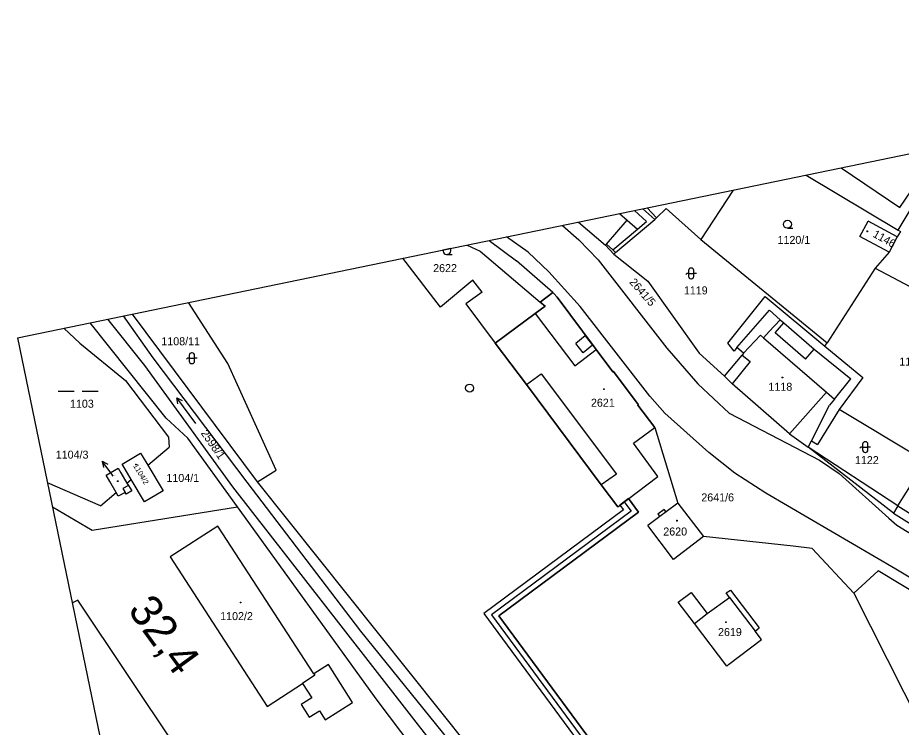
# Model space of a CAD drawing. Extents: x -804166 to -803706, y -1151030 to -1150147.
# Drawn here: x -804166.3 to -804000.6, y -1150280.5 to -1150147.3 of the extents above; entities that cross this region are included whole.
import ezdxf

# ---------------------------------------------------------------- set-up
doc = ezdxf.new("R2010")
doc.units = 0
for name, color, linetype in [('Default', 7, 'Continuous'), ('formát', 7, 'Continuous'), ('kilometráž - vrstava 7', 7, 'Continuous'), ('kn_celek - Cisla parcel pomocna', 7, 'Continuous'), ('kn_celek - Cisla pozemkovych parcel', 7, 'Continuous'), ('kn_celek - Cisla stavebnich parcel', 7, 'Continuous'), ('kn_celek - Hranice parcel', 7, 'Continuous'), ('kn_celek - Vnitrni kresby', 7, 'Continuous'), ('kn_celek - Znacky budov', 7, 'Continuous'), ('kn_celek - Znacky kultur', 7, 'Continuous'), ('plochy - CD', 7, 'Continuous'), ('plochy - SZDC', 7, 'Continuous'), ('plochy - VB', 7, 'Continuous'), ('PSR_C2_2_trasa_Vimperk - Kabelová trasa', 7, 'Continuous')]:
    doc.layers.add(name, color=color, linetype=linetype)

# ---------------------------------------------------------------- blocks, each defined once
blk = doc.blocks.new('803')
at = {"layer": 'Default'}
for p, q in [((-37.9, 0.1), (-7.9, 0.1)), ((7.1, 0.1), (37.1, 0.1))]:
    blk.add_line(p, q, dxfattribs=at)
blk = doc.blocks.new('316')
at = {"layer": 'Default'}
for p, q in [((0.5, 20), (-0.5, 20)), ((-8.3, 10), (-10, 8.1)), ((-5, 10), (-8.3, 10)), ((-5, 15.5), (-5, 4.5)), ((-5, 10), (5, 10)), ((-0.5, 0), (0.5, 0)), ((5, 4.5), (5, 15.5)), ((10, 10), (5, 10))]:
    blk.add_line(p, q, dxfattribs=at)
for centre, start, end in [((-0.5, 15.5), 90, 180), ((0.5, 15.5), 0, 90), ((-0.5, 4.5), 180, 270), ((0.5, 4.5), 270, 0)]:
    blk.add_arc(centre, 4.5, start, end, dxfattribs=at)
blk = doc.blocks.new('304')
at = {"layer": 'Default'}
blk.add_line((-0.1, 0), (9.9, 0), dxfattribs=at)
blk.add_circle((-0.1, 7.5), 7.5, dxfattribs=at)
blk = doc.blocks.new('802')
at = {"layer": 'Default'}
for p, q in [((-30, 0), (30, 0)), ((20, 5), (30, 0)), ((30, 0), (20, -5))]:
    blk.add_line(p, q, dxfattribs=at)
blk = doc.blocks.new('402')
at = {"layer": 'Default'}
for p, q in [((-0.8, 0.8), (0.7, 0.8)), ((-0.8, 0.8), (-0.8, -0.7)), ((0.7, 0.8), (0.7, -0.7)), ((0.7, -0.7), (-0.8, -0.7))]:
    blk.add_line(p, q, dxfattribs=at)
blk = doc.blocks.new('Z61')
at = {"layer": 'Default'}
for p, q in [((0, 0), (30, 0)), ((30, 0), (19.2, 5.3)), ((30, 0), (19.2, -5.3))]:
    blk.add_line(p, q, dxfattribs=at)

msp = doc.modelspace()

# ---------------------------------------------------------------- linework, layer by layer
at = {"layer": 'Default'}
for p, q in [((-804085.16, -1150190.65), (-804086.56, -1150190.94)), ((-804085.82, -1150191.75), (-804084.82, -1150191.75))]:
    msp.add_line(p, q, dxfattribs=at)
msp.add_arc((-804085.82, -1150191), 0.75, 175.2432, 28.0871, dxfattribs=at)
at = {"layer": 'formát'}
for q in [(-803875.43, -1150147.35), (-804123.84, -1150413.06)]:
    msp.add_line((-804166.3, -1150207.4), q, dxfattribs=at)
at = {"layer": 'kilometráž - vrstava 7'}
msp.add_circle((-804081.56, -1150216.84), 0.75, dxfattribs=at)
at = {"layer": 'kn_celek - Cisla parcel pomocna'}
msp.add_line((-804148.4, -1150233.36), (-804148.67, -1150232.99), dxfattribs=at)
at = {"layer": 'kn_celek - Hranice parcel'}
for p, q in [((-804000.88, -1150182.97), (-803994.65, -1150173.69)), ((-804001.24, -1150187.2), (-803993.82, -1150174.86)), ((-804018.48, -1150176.88), (-804001.24, -1150187.2)), ((-804011.92, -1150175.53), (-804000.88, -1150182.97)), ((-804032.16, -1150179.71), (-804038.18, -1150188.96)), ((-804048.27, -1150183.03), (-804046.51, -1150184.91)), ((-804046.51, -1150184.91), (-804044.69, -1150183.13)), ((-804044.69, -1150183.13), (-804038.18, -1150188.96)), ((-804054.22, -1150191.39), (-804046.83, -1150185.22)), ((-804046.83, -1150185.22), (-804046.51, -1150184.91)), ((-804064.14, -1150186.31), (-804061.09, -1150189.04)), ((-804061.17, -1150185.69), (-804056.08, -1150190.02)), ((-804008.37, -1150188.37), (-804006.85, -1150185.52)), ((-804001.37, -1150188.44), (-804006.85, -1150185.52)), ((-804070.61, -1150191.34), (-804074.65, -1150188.48)), ((-804002.9, -1150191.34), (-804008.37, -1150188.37)), ((-804001.37, -1150188.44), (-804002.9, -1150191.34)), ((-804000.78, -1150187.47), (-804001.37, -1150188.44)), ((-804001.24, -1150187.2), (-804000.78, -1150187.47)), ((-804082.03, -1150190), (-804079.56, -1150191.12)), ((-804077.91, -1150189.15), (-804072.79, -1150192.97)), ((-804061.09, -1150189.04), (-804057.45, -1150192.8)), ((-804056.08, -1150190.02), (-804054.55, -1150191.72)), ((-804038.18, -1150188.96), (-804014.54, -1150208.35)), ((-804079.56, -1150191.12), (-804068.34, -1150200.69)), ((-804066.7, -1150195.01), (-804070.61, -1150191.34)), ((-804054.22, -1150191.39), (-804054.55, -1150191.72)), ((-804054.55, -1150191.72), (-804048.14, -1150196.79)), ((-804002.9, -1150191.34), (-804005.52, -1150194.37)), ((-804087, -1150201.67), (-804094.06, -1150192.49)), ((-804065.96, -1150198.88), (-804072.79, -1150192.97)), ((-804057.45, -1150192.8), (-804044.6, -1150209.37)), ((-804060.81, -1150201.5), (-804066.7, -1150195.01)), ((-804005.52, -1150194.37), (-804014.54, -1150208.35)), ((-804005.52, -1150194.37), (-803982.57, -1150206.4)), ((-804080.94, -1150196.58), (-804087, -1150201.67)), ((-804079.2, -1150198.82), (-804080.94, -1150196.58)), ((-804048.14, -1150196.79), (-804038.53, -1150210.29)), ((-804079.2, -1150198.82), (-804082.27, -1150201.05)), ((-804068.34, -1150200.69), (-804065.96, -1150198.88)), ((-804065.78, -1150199.08), (-804065.96, -1150198.88)), ((-804065.78, -1150199.08), (-804065.16, -1150199.8)), ((-804065.16, -1150199.8), (-804058.02, -1150209.36)), ((-804033.15, -1150208.42), (-804026.17, -1150199.66)), ((-804026.17, -1150199.66), (-804014.94, -1150208.97)), ((-804126.9, -1150212.23), (-804134.27, -1150200.79)), ((-804082.27, -1150201.05), (-804076.76, -1150208.41)), ((-804069.26, -1150202.82), (-804067.42, -1150201.47)), ((-804067.42, -1150201.47), (-804068.34, -1150200.69)), ((-804047.79, -1150218.32), (-804060.81, -1150201.5)), ((-804121.35, -1150234.4), (-804144.78, -1150202.96)), ((-804076.76, -1150208.41), (-804069.26, -1150202.82)), ((-804138.44, -1150222.48), (-804152.68, -1150204.59)), ((-804157.64, -1150205.61), (-804154.63, -1150208.39)), ((-804154.63, -1150208.39), (-804146.05, -1150215.39)), ((-804070.92, -1150216.16), (-804076.76, -1150208.41)), ((-804031.94, -1150209.94), (-804033.15, -1150208.42)), ((-804014.94, -1150208.97), (-804014.54, -1150208.35)), ((-804058.02, -1150209.36), (-804057.84, -1150209.6)), ((-804057.84, -1150209.6), (-804054.7, -1150213.8)), ((-804044.6, -1150209.37), (-804038.78, -1150216.01)), ((-804031.44, -1150209.25), (-804031.94, -1150209.94)), ((-804030.19, -1150210.3), (-804031.44, -1150209.25)), ((-804014.94, -1150208.97), (-804007.83, -1150214.86)), ((-804038.53, -1150210.29), (-804033.76, -1150214.58)), ((-804033.76, -1150214.58), (-804030.47, -1150210.63)), ((-804030.19, -1150210.3), (-804030.47, -1150210.63)), ((-804117.86, -1150232.22), (-804126.9, -1150212.23)), ((-804054.7, -1150213.8), (-804054.58, -1150213.71)), ((-804054.58, -1150213.71), (-804049.93, -1150219.91)), ((-804033.76, -1150214.58), (-804032.36, -1150216.05)), ((-804007.83, -1150214.86), (-804012.29, -1150220.87)), ((-804146.05, -1150215.39), (-804138.03, -1150226.06)), ((-804056.87, -1150234.96), (-804070.92, -1150216.16)), ((-804038.78, -1150216.01), (-804032.88, -1150221.57)), ((-804021.57, -1150225.42), (-804032.36, -1150216.05)), ((-804044.95, -1150221.51), (-804047.79, -1150218.32)), ((-804049.93, -1150219.91), (-804050.01, -1150220.06)), ((-804050.01, -1150220.06), (-804046.86, -1150224.2)), ((-804036.73, -1150228.89), (-804044.95, -1150221.51)), ((-804032.88, -1150221.57), (-804015.93, -1150230.34)), ((-804012.29, -1150220.87), (-804016.36, -1150227.42)), ((-803996.21, -1150230.54), (-804012.29, -1150220.87)), ((-804134.41, -1150226.23), (-804138.44, -1150222.48)), ((-804050.84, -1150227.18), (-804046.86, -1150224.2)), ((-804046.86, -1150224.2), (-804042.5, -1150238.42)), ((-804138.03, -1150226.06), (-804137.9, -1150227.9)), ((-804125.07, -1150239.09), (-804134.41, -1150226.23)), ((-804021.57, -1150225.42), (-804018.08, -1150227.93)), ((-804018.08, -1150227.93), (-804017.43, -1150226.7)), ((-804017.43, -1150226.7), (-804016.36, -1150227.42)), ((-804141.9, -1150231.32), (-804137.9, -1150227.9)), ((-804046.26, -1150233.41), (-804050.84, -1150227.18)), ((-804002.08, -1150240.27), (-804018.08, -1150227.93)), ((-804146.72, -1150231.08), (-804143.27, -1150229.04)), ((-804143.27, -1150229.04), (-804142.98, -1150229.52)), ((-804142.98, -1150229.52), (-804141.9, -1150231.32)), ((-804031.83, -1150232.79), (-804036.73, -1150228.89)), ((-804146.13, -1150232.06), (-804146.72, -1150231.08)), ((-804141.9, -1150231.32), (-804139.01, -1150236.11)), ((-804015.93, -1150230.34), (-804012.27, -1150232.87)), ((-804149.69, -1150233.15), (-804147.45, -1150231.88)), ((-804148.99, -1150234.38), (-804149.69, -1150233.15)), ((-804147.45, -1150231.88), (-804146.95, -1150232.73)), ((-804146.95, -1150232.73), (-804145.82, -1150234.66)), ((-804145, -1150233.96), (-804146.13, -1150232.06)), ((-804121.35, -1150234.4), (-804117.86, -1150232.22)), ((-804053.79, -1150239.08), (-804046.26, -1150233.41)), ((-804026.04, -1150236.52), (-804031.83, -1150232.79)), ((-804012.27, -1150232.87), (-804002.98, -1150241.24)), ((-804150.79, -1150238.91), (-804160.69, -1150234.59)), ((-804147.85, -1150236.4), (-804148.99, -1150234.38)), ((-804145.82, -1150234.66), (-804145, -1150233.96)), ((-804145.82, -1150234.66), (-804145.55, -1150235.12)), ((-804142.49, -1150238.15), (-804145, -1150233.96)), ((-804081.21, -1150284.7), (-804121.35, -1150234.4)), ((-804053.79, -1150239.08), (-804056.87, -1150234.96)), ((-804150.79, -1150238.91), (-804147.85, -1150236.4)), ((-804147.43, -1150237.14), (-804147.85, -1150236.4)), ((-804146.14, -1150236.42), (-804147.43, -1150237.14)), ((-804145.97, -1150236.71), (-804146.14, -1150236.42)), ((-804144.92, -1150236.11), (-804145.97, -1150236.71)), ((-804145.55, -1150235.12), (-804144.92, -1150236.11)), ((-804139.01, -1150236.11), (-804142.49, -1150238.15)), ((-804001.67, -1150250.78), (-804026.04, -1150236.52)), ((-804001.25, -1150238.93), (-803998.92, -1150235.16)), ((-804159.75, -1150239.13), (-804152.35, -1150243.49)), ((-804152.35, -1150243.49), (-804125.07, -1150239.09)), ((-804098.91, -1150275.35), (-804125.07, -1150239.09)), ((-804045.09, -1150239.61), (-804046.26, -1150240.46)), ((-804044.74, -1150240.08), (-804045.09, -1150239.61)), ((-804042.5, -1150238.42), (-804044.74, -1150240.08)), ((-804042.5, -1150238.42), (-804037.73, -1150244.68)), ((-804001.25, -1150238.93), (-804002.08, -1150240.27)), ((-804045.9, -1150240.94), (-804048.13, -1150242.59)), ((-804046.26, -1150240.46), (-804045.9, -1150240.94)), ((-804002.98, -1150241.24), (-804001.47, -1150242.58)), ((-804002.08, -1150240.27), (-803993.33, -1150245.84)), ((-804128.74, -1150242.73), (-804137.71, -1150248.5)), ((-804110.74, -1150270.45), (-804128.74, -1150242.73)), ((-804043.35, -1150248.97), (-804048.13, -1150242.59)), ((-804001.47, -1150242.58), (-803965.84, -1150264.29)), ((-804037.73, -1150244.68), (-804043.35, -1150248.97)), ((-804020.87, -1150246.51), (-804037.73, -1150244.68)), ((-804017.32, -1150246.9), (-804020.87, -1150246.51)), ((-804017.32, -1150246.9), (-804009.55, -1150255.32)), ((-804137.71, -1150248.5), (-804119.52, -1150276.54)), ((-804004.96, -1150251.13), (-804009.55, -1150255.32)), ((-803981.13, -1150265.6), (-804004.96, -1150251.13)), ((-803962.74, -1150274.61), (-804001.67, -1150250.78)), ((-804033.46, -1150255.26), (-804032.63, -1150254.75)), ((-804032.63, -1150254.75), (-804027.25, -1150261.82)), ((-804042.49, -1150256.99), (-804040.01, -1150255.2)), ((-804040.01, -1150255.2), (-804037.01, -1150259.13)), ((-804037.01, -1150259.13), (-804032.83, -1150256.09)), ((-804032.83, -1150256.09), (-804033.46, -1150255.26)), ((-804009.55, -1150255.32), (-803997.02, -1150280.06)), ((-804155.03, -1150256.65), (-804156.03, -1150257.15)), ((-804116.64, -1150313.9), (-804155.03, -1150256.65)), ((-804039.39, -1150261.01), (-804042.49, -1150256.99)), ((-804033.36, -1150268.97), (-804039.39, -1150261.01)), ((-804028.04, -1150262.42), (-804027.25, -1150261.82)), ((-804026.84, -1150264.01), (-804028.04, -1150262.42)), ((-804033, -1150268.7), (-804026.84, -1150264.01)), ((-804108.01, -1150268.68), (-804110.74, -1150270.45)), ((-804103.54, -1150275.84), (-804108.01, -1150268.68)), ((-804033, -1150268.7), (-804033.36, -1150268.97)), ((-804119.52, -1150276.54), (-804112.91, -1150272.23)), ((-804112.91, -1150272.23), (-804111.15, -1150274.93)), ((-804111.15, -1150274.93), (-804113.12, -1150276.17)), ((-804113.12, -1150276.17), (-804111.63, -1150278.57)), ((-804108.65, -1150279.08), (-804103.54, -1150275.84)), ((-804036.11, -1150358.19), (-804098.91, -1150275.35)), ((-804111.63, -1150278.57), (-804109.69, -1150277.35)), ((-804109.69, -1150277.35), (-804108.65, -1150279.08))]:
    msp.add_line(p, q, dxfattribs=at)
at = {"layer": 'kn_celek - Vnitrni kresby'}
for p, q in [((-804050.65, -1150183.52), (-804048.38, -1150185.61)), ((-804049.07, -1150183.2), (-804046.83, -1150185.22)), ((-804055.9, -1150189.81), (-804052.04, -1150185.32)), ((-804053.46, -1150184.1), (-804052.04, -1150185.32)), ((-804052.04, -1150185.32), (-804050.07, -1150187.02)), ((-804054.72, -1150190.92), (-804050.07, -1150187.02)), ((-804050.07, -1150187.02), (-804048.38, -1150185.61)), ((-804056.08, -1150190.02), (-804055.9, -1150189.81)), ((-804055.9, -1150189.81), (-804054.72, -1150190.92)), ((-804054.72, -1150190.92), (-804054.22, -1150191.39)), ((-804140.87, -1150211.16), (-804146.48, -1150203.31)), ((-804069.26, -1150202.82), (-804061.84, -1150212.67)), ((-804031.44, -1150209.25), (-804025.36, -1150202.24)), ((-804025.36, -1150202.24), (-804023.32, -1150204.02)), ((-804149.44, -1150203.92), (-804142.53, -1150212.59)), ((-804025.41, -1150206.25), (-804023.32, -1150204.02)), ((-804024.3, -1150206.46), (-804022.66, -1150204.58)), ((-804023.32, -1150204.02), (-804022.66, -1150204.58)), ((-804022.66, -1150204.58), (-804016.95, -1150209.55)), ((-804030.19, -1150210.3), (-804027.02, -1150206.93)), ((-804027.02, -1150206.93), (-804026.48, -1150207.39)), ((-804026.48, -1150207.39), (-804025.41, -1150206.25)), ((-804018.57, -1150211.4), (-804024.3, -1150206.46)), ((-804059.9, -1150207.04), (-804061.67, -1150208.45)), ((-804060.27, -1150210.21), (-804061.67, -1150208.45)), ((-804059.9, -1150207.04), (-804058.5, -1150208.8)), ((-804026.48, -1150207.39), (-804014.63, -1150217.6)), ((-804061.84, -1150212.67), (-804057.84, -1150209.6)), ((-804058.5, -1150208.8), (-804060.27, -1150210.21)), ((-804018.57, -1150211.4), (-804016.95, -1150209.55)), ((-804016.95, -1150209.55), (-804010.08, -1150215.13)), ((-804123.25, -1150234.46), (-804140.87, -1150211.16)), ((-804028.99, -1150211.86), (-804032.36, -1150216.05)), ((-804030.47, -1150210.63), (-804028.99, -1150211.86)), ((-804142.53, -1150212.59), (-804126, -1150235.35)), ((-804070.92, -1150216.16), (-804068.15, -1150214.19)), ((-804068.15, -1150214.19), (-804054.05, -1150233)), ((-804013.16, -1150218.89), (-804010.08, -1150215.13)), ((-804021.57, -1150225.42), (-804014.63, -1150217.6)), ((-804014.63, -1150217.6), (-804013.16, -1150218.89)), ((-804017.43, -1150226.7), (-804014.1, -1150220.04)), ((-804013.16, -1150218.89), (-804014.1, -1150220.04)), ((-804001.25, -1150238.93), (-804018.08, -1150227.93)), ((-804054.05, -1150233), (-804056.87, -1150234.96)), ((-804101.97, -1150262.44), (-804123.25, -1150234.46)), ((-804145.55, -1150235.12), (-804146.56, -1150235.7)), ((-804146.56, -1150235.7), (-804146.14, -1150236.42)), ((-804126, -1150235.35), (-804105.26, -1150261.99)), ((-804001.25, -1150238.93), (-803998.77, -1150240.51)), ((-804044.74, -1150240.08), (-804045.9, -1150240.94)), ((-804032.83, -1150256.09), (-804028.04, -1150262.42)), ((-804039.39, -1150261.01), (-804037.01, -1150259.13)), ((-804105.26, -1150261.99), (-804080.36, -1150294)), ((-804083.56, -1150285.18), (-804101.97, -1150262.44)), ((-804110.57, -1150270.67), (-804112.91, -1150272.23)), ((-804110.74, -1150270.45), (-804110.57, -1150270.67))]:
    msp.add_line(p, q, dxfattribs=at)
at = {"layer": 'plochy - CD'}
for p, q in [((-804078.87, -1150259.13), (-804006.89, -1150356.88)), ((-804005.25, -1150355.72), (-804076.08, -1150259.54))]:
    msp.add_line(p, q, dxfattribs=at)
for points in [[(-804051.79, -1150237.57), (-804053.39, -1150238.78), (-804052.7, -1150239.7), (-804078.87, -1150259.13)], [(-804076.08, -1150259.54), (-804049.9, -1150240.12), (-804051.79, -1150237.57)]]:
    msp.add_lwpolyline(points, dxfattribs=at)
at = {"layer": 'plochy - SZDC'}
for p, q in [((-804065.96, -1150198.88), (-804068.34, -1150200.69)), ((-804065.78, -1150199.08), (-804065.96, -1150198.88)), ((-804065.16, -1150199.8), (-804065.78, -1150199.08)), ((-804058.02, -1150209.36), (-804065.16, -1150199.8)), ((-804067.42, -1150201.47), (-804069.26, -1150202.82)), ((-804068.34, -1150200.69), (-804067.42, -1150201.47)), ((-804069.26, -1150202.82), (-804076.76, -1150208.41)), ((-804076.76, -1150208.41), (-804070.92, -1150216.16)), ((-804057.84, -1150209.6), (-804058.02, -1150209.36)), ((-804054.7, -1150213.8), (-804057.84, -1150209.6)), ((-804054.58, -1150213.71), (-804054.7, -1150213.8)), ((-804049.93, -1150219.91), (-804054.58, -1150213.71)), ((-804070.92, -1150216.16), (-804056.87, -1150234.96)), ((-804050.01, -1150220.06), (-804049.93, -1150219.91)), ((-804046.86, -1150224.2), (-804050.01, -1150220.06)), ((-804050.84, -1150227.18), (-804046.86, -1150224.2)), ((-804046.26, -1150233.41), (-804050.84, -1150227.18)), ((-804053.79, -1150239.08), (-804046.26, -1150233.41)), ((-804056.87, -1150234.96), (-804053.79, -1150239.08))]:
    msp.add_line(p, q, dxfattribs=at)
at = {"layer": 'plochy - VB'}
for p, q in [((-804078.87, -1150259.13), (-804006.89, -1150356.88)), ((-804076.08, -1150259.54), (-804005.25, -1150355.72))]:
    msp.add_line(p, q, dxfattribs=at)
for points in [[(-804051.79, -1150237.57), (-804053.39, -1150238.78), (-804052.7, -1150239.7), (-804078.87, -1150259.13)], [(-804051.79, -1150237.57), (-804049.9, -1150240.12), (-804076.08, -1150259.54)]]:
    msp.add_lwpolyline(points, dxfattribs=at)
at = {"layer": 'PSR_C2_2_trasa_Vimperk - Kabelová trasa'}
msp.add_line((-804077.48, -1150259.34), (-804006.07, -1150356.3), dxfattribs=at)
msp.add_lwpolyline([(-804052.62, -1150238.13), (-804051.3, -1150239.91), (-804077.48, -1150259.34)], dxfattribs=at)

# ---------------------------------------------------------------- block references
at = {"layer": 'kn_celek - Cisla parcel pomocna', "xscale": 0.1, "yscale": 0.09999999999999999, "rotation": 126.30717000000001}
msp.add_blockref('Z61', (-804148.67, -1150232.99), dxfattribs=at)
at = {"layer": 'kn_celek - Znacky budov', "xscale": 0.1, "yscale": 0.10000000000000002}
for p in [(-804007.03, -1150187.43), (-804022.92, -1150214.84), (-804056.4, -1150217.06), (-804144.13, -1150231.19), (-804147.54, -1150234.3), (-804042.71, -1150241.72), (-804124.52, -1150257.05), (-804033.5, -1150260.76)]:
    msp.add_blockref('402', p, dxfattribs=at)
at = {"layer": 'kn_celek - Znacky kultur', "xscale": 0.1, "yscale": 0.10000000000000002}
for name, p in [('304', (-804021.96, -1150186.86)), ('316', (-804040.02, -1150196.33)), ('316', (-804133.63, -1150212.24)), ('803', (-804154.92, -1150217.42)), ('316', (-804007.37, -1150228.9))]:
    msp.add_blockref(name, p, dxfattribs=at)
at = {"layer": 'kn_celek - Znacky kultur', "xscale": 0.10000000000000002, "yscale": 0.1, "rotation": 126.86994000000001}
msp.add_blockref('802', (-804134.67, -1150221.08), dxfattribs=at)

# ---------------------------------------------------------------- texts
at = {"layer": 'kilometráž - vrstava 7'}
msp.add_text('32,4', height=6, rotation=306.0318, dxfattribs=at).set_placement((-804145.79, -1150258.51))
at = {"layer": 'kn_celek - Cisla parcel pomocna'}
msp.add_text('1104/3', height=1.5, dxfattribs=at).set_placement((-804159.16, -1150230.07))
at = {"layer": 'kn_celek - Cisla pozemkovych parcel'}
for s, p in [('1120/1', (-804023.83, -1150189.79)), ('2622', (-804088.4, -1150195.08)), ('1119', (-804041.39, -1150199.26)), ('1108/11', (-804139.36, -1150208.8)), ('1121', (-804000.99, -1150212.61)), ('1103', (-804156.49, -1150220.52)), ('1122', (-804009.32, -1150231.1)), ('1104/1', (-804138.41, -1150234.44)), ('2641/6', (-804038.12, -1150238.09))]:
    msp.add_text(s, height=1.5, dxfattribs=at).set_placement(p)
for s, rotation, p in [('2641/5', 311.4, (-804051.71, -1150197.03)), ('2598/1', 304.7067, (-804132.02, -1150225.3))]:
    msp.add_text(s, height=1.5, rotation=rotation, dxfattribs=at).set_placement(p)
at = {"layer": 'kn_celek - Cisla stavebnich parcel'}
for s, height, rotation, p in [('1146', 1.5, 330.8431, (-804006.1, -1150188.38)), ('1104/2', 1, 300.6, (-804144.67, -1150231.42))]:
    msp.add_text(s, height=height, rotation=rotation, dxfattribs=at).set_placement(p)
for s, height, p in [('1118', 1.5, (-804025.53, -1150217.33)), ('2621', 1.5, (-804058.81, -1150220.33)), ('1104/3', 0.1, (-804148.4, -1150233.33)), ('2620', 1.5, (-804045.25, -1150244.49)), ('1102/2', 1.5, (-804128.33, -1150260.36)), ('2619', 1.5, (-804034.99, -1150263.35))]:
    msp.add_text(s, height=height, dxfattribs=at).set_placement(p)

doc.saveas('drawing.dxf')
